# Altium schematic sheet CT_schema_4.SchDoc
size 299 x 185 mm
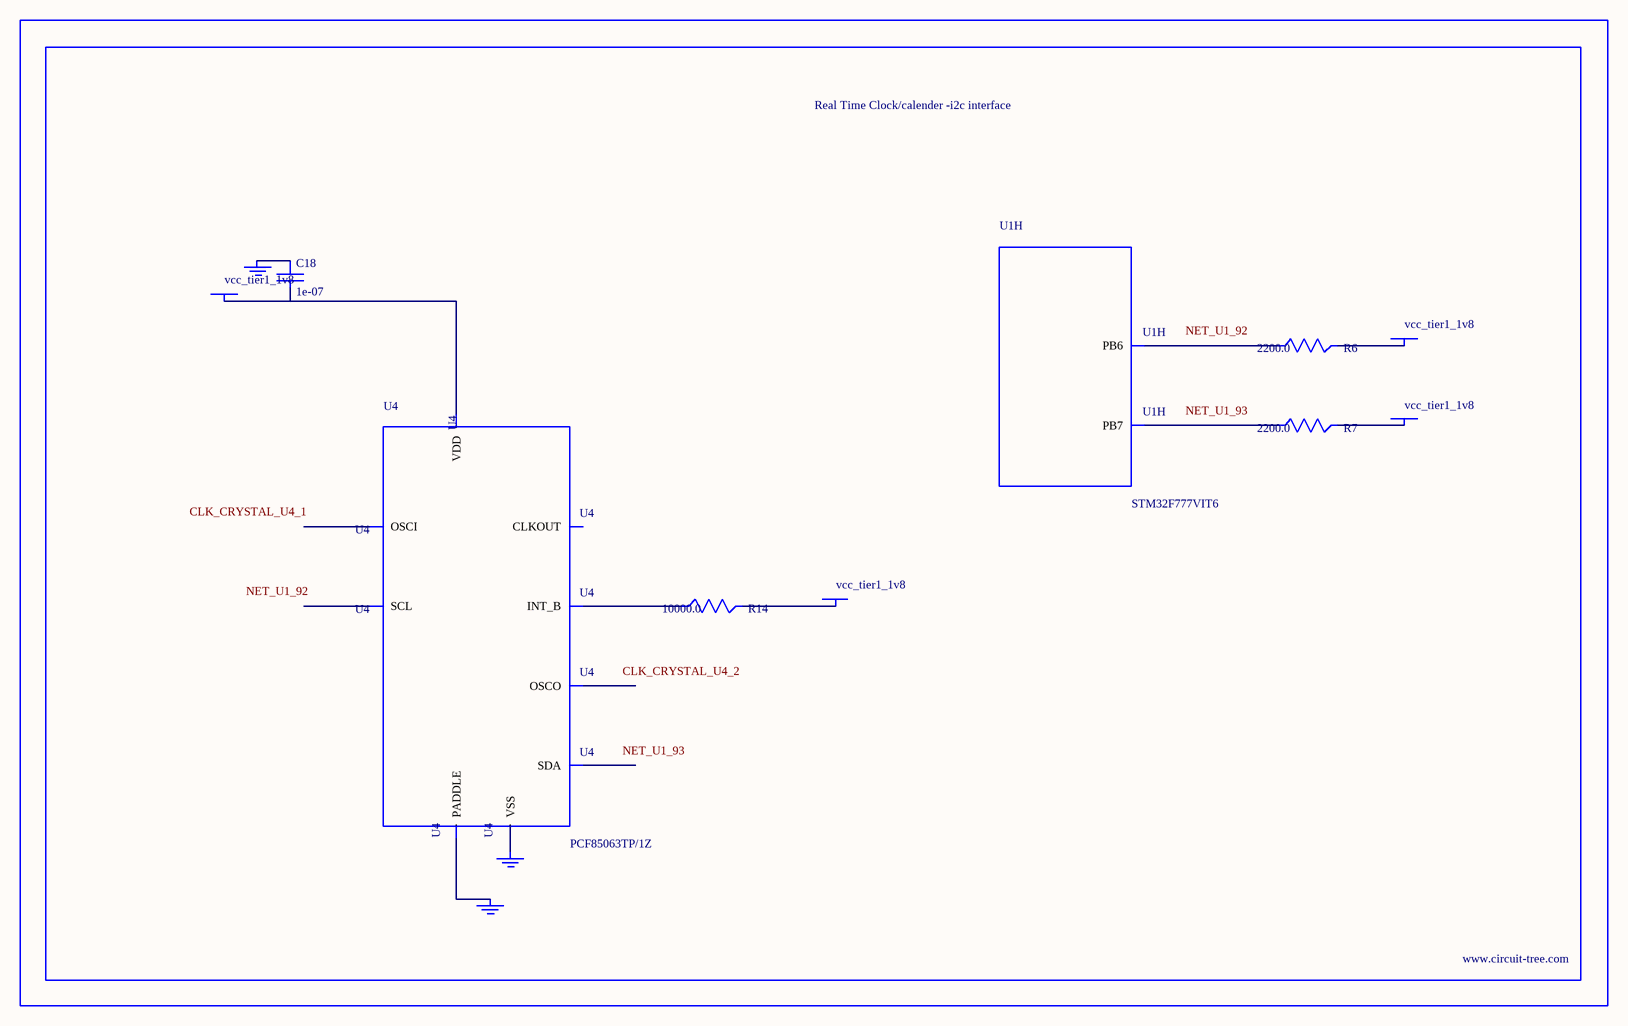
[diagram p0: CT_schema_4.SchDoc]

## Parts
BORDER3  (no value)
C18  1e-07  [C0402]
GND_INSTANCE_3_0  (no value)
GND_INSTANCE_3_1  (no value)
GND_INSTANCE_3_2  (no value)
POWER_INSTANCE_3_0  vcc_tier1_1v8
POWER_INSTANCE_3_1  vcc_tier1_1v8
POWER_INSTANCE_3_2  vcc_tier1_1v8
POWER_INSTANCE_3_3  vcc_tier1_1v8
R6  2200.0  [R0603]
R7  2200.0  [R0603]
R14  10000.0  [R0603]
U1  STM32F777VIT6  [LQFP100]  (part H of 11)
U4  PCF85063TP/1Z  [SON-8]

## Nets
NetC18_1: C18.1 GND_INSTANCE_3_0.0(GND)
NetC18_2: C18.2 POWER_INSTANCE_3_1.0(PWR) U4.8(VDD)
NetGND_INSTANCE_3_1_0: GND_INSTANCE_3_1.0(GND) U4.PAD(PADDLE)
NetGND_INSTANCE_3_2_0: GND_INSTANCE_3_2.0(GND) U4.4(VSS)
NetPOWER_INSTANCE_3_0_0: POWER_INSTANCE_3_0.0(PWR) R14.2
NetPOWER_INSTANCE_3_2_0: POWER_INSTANCE_3_2.0(PWR) R6.2
NetPOWER_INSTANCE_3_3_0: POWER_INSTANCE_3_3.0(PWR) R7.2
NetR6_1: R6.1 U1.92(PB6)
NetR7_1: R7.1 U1.93(PB7)
NetR14_1: R14.1 U4.3(INT_B)

Not connected (* = marked no-connect by the designer): U4 1(OSCI) 2(OSCO) 5(SDA) 6(SCL) 7(CLKOUT)

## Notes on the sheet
- Labels drawn without touching a wire or pin: CLK_CRYSTAL_U4_1, CLK_CRYSTAL_U4_2, NET_U1_92, NET_U1_93

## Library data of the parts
BORDER3 = BORDER_PAGE3
C18 = C0402C104K3RACTU
GND_INSTANCE_3_0-GND_INSTANCE_3_2 = GND
POWER_INSTANCE_3_0-POWER_INSTANCE_3_3 = PWR
R6 R7 = RC0603JR-072K2L
R14 = RC0603JR-0710KL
